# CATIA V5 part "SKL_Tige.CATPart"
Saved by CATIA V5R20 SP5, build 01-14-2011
Part number: SKL_Tige
Publications: "Point.1", "Point.3", "Droite.1", "Plan.1", "Plan.3", "Plan.4"
Bounding box of the stored display mesh (mm): x -20 to -20, y 20 to 160, z 0 to 0
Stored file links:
  F:\Catia_finish\SKL_Tige.CATPart
  F:\Catia_finish\ASS_SKL.CATProduct
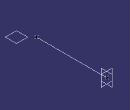
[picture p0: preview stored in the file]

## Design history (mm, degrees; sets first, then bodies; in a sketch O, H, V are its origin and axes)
Set1
  Point1: linked copy from another document
  Point2: linked copy from another document
  Plane1: linked copy from another document
Set2 "set geometrique"
  Point3: (0, 0, 0), relative to Point1
  Point4: (0, 0, 0), relative to Point2
  Line1: type PtPt, FirstPoint Point4, SecondPoint Point3
  Plane2: type Offset, RefPlane Plane1, Offset 0
  Plane3: type OffsetPt, RefPlane zx-plane, RefPoint Point4
  Plane4: type OffsetPt, RefPlane yz-plane, RefPoint Point2
Body1 (main body)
